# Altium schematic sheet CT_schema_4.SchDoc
size 278 x 170 mm
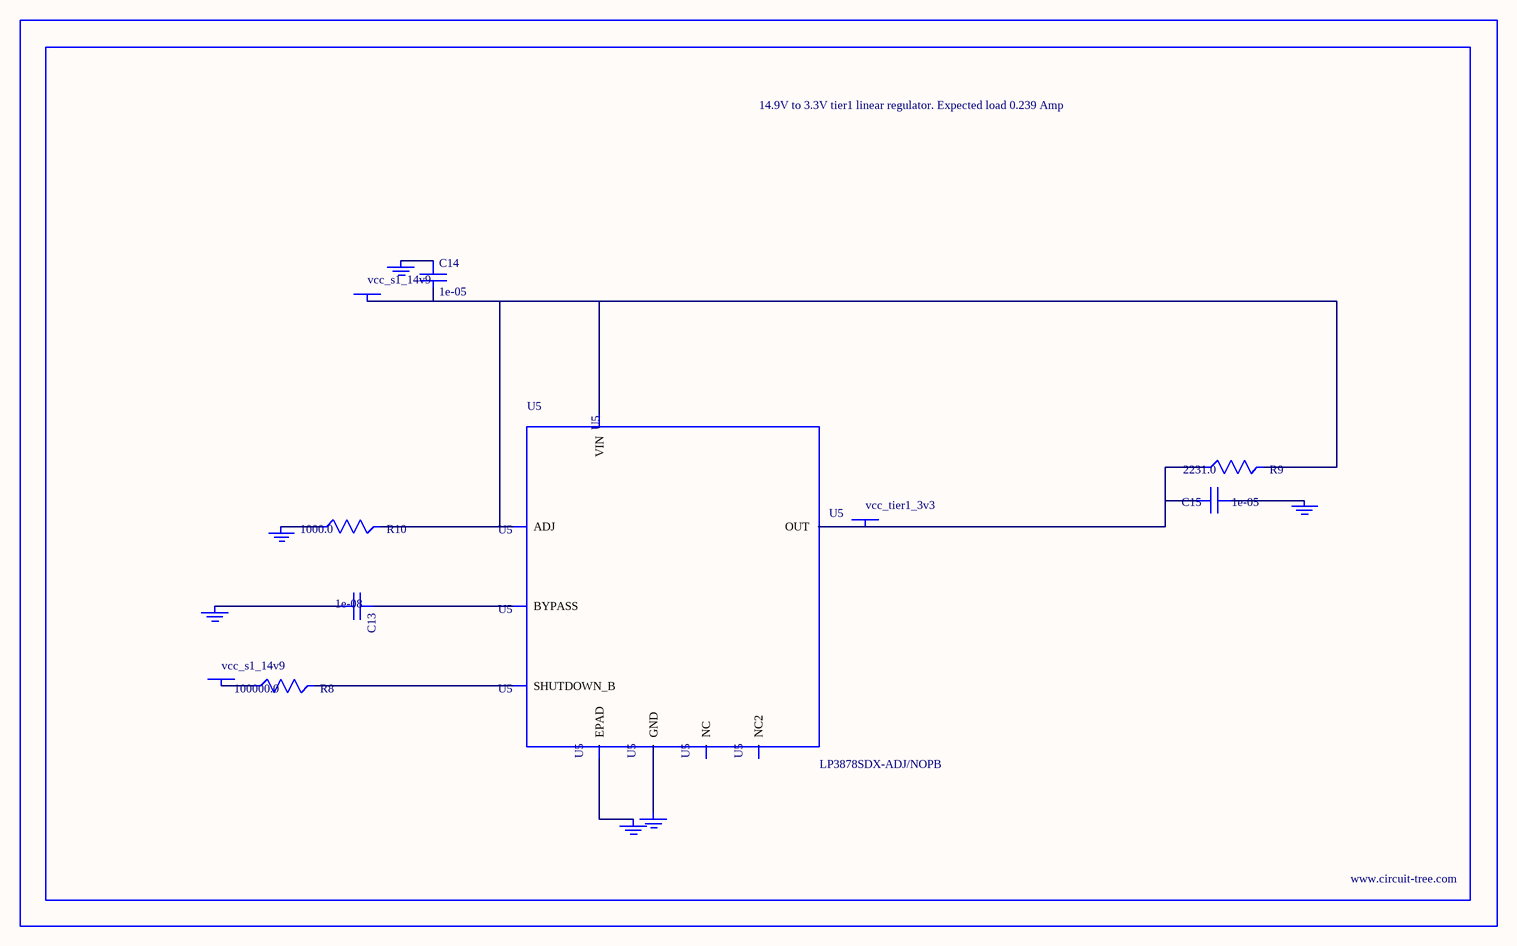
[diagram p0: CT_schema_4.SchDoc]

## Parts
BORDER3  (no value)
C13  1e-08  [C0402]
C14  1e-05  [C1210]
C15  1e-05  [C1210]
GND_INSTANCE_3_0  (no value)
GND_INSTANCE_3_1  (no value)
GND_INSTANCE_3_2  (no value)
GND_INSTANCE_3_3  (no value)
GND_INSTANCE_3_4  (no value)
GND_INSTANCE_3_5  (no value)
POWER_INSTANCE_3_0  vcc_s1_14v9
POWER_INSTANCE_3_1  vcc_s1_14v9
POWER_INSTANCE_3_2  vcc_tier1_3v3
R8  100000.0  [R0603]
R9  2231.0  [R0603]
R10  1000.0  [R0603]
U5  LP3878SDX-ADJ/NOPB  [WSON-8]

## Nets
NetC13_1: C13.1 U5.1(BYPASS)
NetC13_2: C13.2 GND_INSTANCE_3_0.0(GND)
NetC14_1: C14.1 GND_INSTANCE_3_1.0(GND)
NetC14_2: C14.2 POWER_INSTANCE_3_0.0(PWR) R9.2 R10.2 U5.4(VIN) U5.6(ADJ)
NetC15_1: C15.1 GND_INSTANCE_3_2.0(GND)
NetC15_2: C15.2 POWER_INSTANCE_3_2.0(PWR) R9.1 U5.5(OUT)
NetGND_INSTANCE_3_3_0: GND_INSTANCE_3_3.0(GND) R10.1
NetGND_INSTANCE_3_4_0: GND_INSTANCE_3_4.0(GND) U5.PAD(EPAD)
NetGND_INSTANCE_3_5_0: GND_INSTANCE_3_5.0(GND) U5.3(GND)
NetPOWER_INSTANCE_3_1_0: POWER_INSTANCE_3_1.0(PWR) R8.1
NetR8_2: R8.2 U5.8(SHUTDOWN_B)

Not connected (* = marked no-connect by the designer): U5 2(NC) 7(NC2)

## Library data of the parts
BORDER3 = BORDER_PAGE3
C13 = C0402C103K3RAC
C14 = C1210C106K5PACTU
C15 = GRM32DR61E106MA12L
GND_INSTANCE_3_0-GND_INSTANCE_3_5 = GND
POWER_INSTANCE_3_0-POWER_INSTANCE_3_2 = PWR
R8 = RC0603JR-07100KL
R9 = R9
R10 = RC0603JR-071KL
